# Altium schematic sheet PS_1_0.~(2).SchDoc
size A4
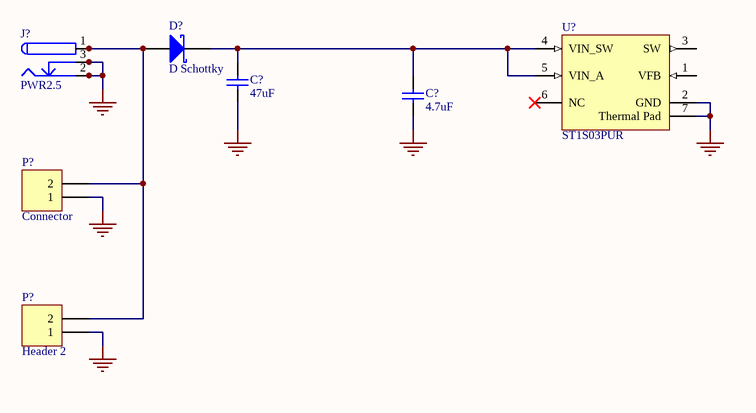
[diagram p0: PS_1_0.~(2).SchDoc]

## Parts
(Parts that share a designator on the sheet are numbered #1, #2 ... from top to bottom, then left to right.)
C?#1  47uF  [C0805]
C?#2  4.7uF  [C0805]
D?  D Schottky  [SMB]
J?  PWR2.5  [KLD-0202]
P?#1  Connector  [HDR1X2]
P?#2  Header 2  [HDR1X2]
U?  ST1S03PUR  [DFN6D_M]

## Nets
GND: C?#1.2 C?#2.2 J?.2 J?.2A J?.2B J?.3 J?.3A J?.3B P?#1.1 P?#2.1 U?.2(GND) U?.7(Thermal_Pad)
NetC?#1_1: C?#1.1 C?#2.1 D?.2(K) U?.4(VIN_SW) U?.5(VIN_A)
NetD?_1: D?.1(A) J?.1 J?.1A J?.1B P?#1.2 P?#2.2

Not connected (* = marked no-connect by the designer): U? 1(VFB) 3(SW) 6(NC)*

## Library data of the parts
C?#1 C?#2 = Cap Semi: Capacitor (Semiconductor SIM Model)
D? = D Schottky: Schottky Diode
J? = PWR2.5: Low Voltage Power Supply Connector
P?#1 P?#2 = Header 2: Header, 2-Pin
U? = ST1S03PUR: 1.5 A, 1.5 MHz adjustable, step-down switching regulator, DFN6D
